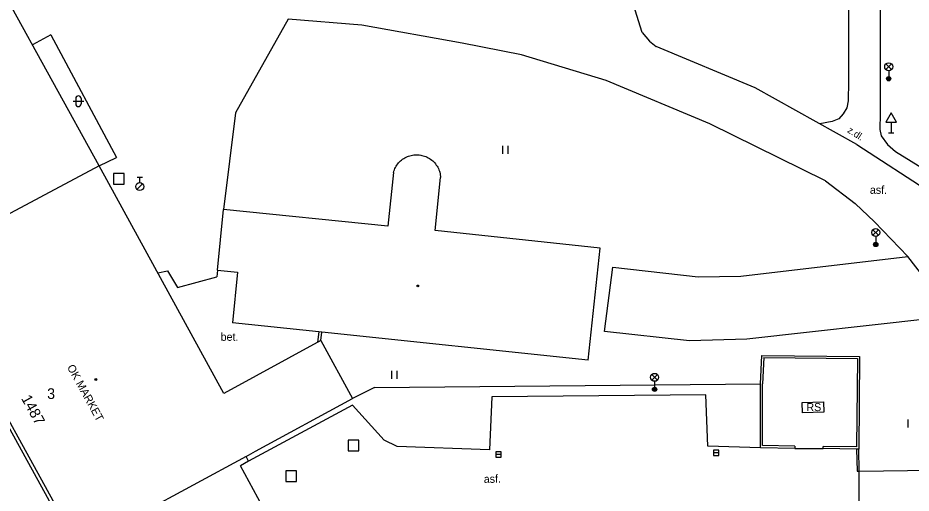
# Model space of a CAD drawing. Extents: x -641829 to -641525, y -1114855 to -1114359.
# Drawn here: x -641715.8 to -641632.1, y -1114774 to -1114729.4 of the extents above; entities that cross this region are included whole.
import ezdxf

# ---------------------------------------------------------------- set-up
doc = ezdxf.new("R2010")
doc.units = 0
for name, color, linetype in [('Vrstva 10', 7, 'Continuous'), ('Vrstva 11', 7, 'Continuous'), ('Vrstva 24', 7, 'Continuous'), ('Vrstva 26', 7, 'Continuous'), ('Vrstva 27', 7, 'Continuous'), ('Vrstva 28', 7, 'Continuous'), ('Vrstva 33', 7, 'Continuous'), ('Vrstva 34', 7, 'Continuous'), ('Vrstva 36', 7, 'Continuous'), ('Vrstva 39', 7, 'Continuous'), ('Vrstva 40', 7, 'Continuous'), ('Vrstva 41', 7, 'Continuous'), ('Vrstva 46', 7, 'Continuous'), ('Vrstva 47', 7, 'Continuous'), ('Vrstva 5', 7, 'Continuous'), ('Vrstva 7', 7, 'Continuous'), ('Vrstva 8', 7, 'Continuous')]:
    doc.layers.add(name, color=color, linetype=linetype)

msp = doc.modelspace()

# ---------------------------------------------------------------- linework, layer by layer
at = {"layer": 'Vrstva 10'}
for p, q in [((-641657.27, -1114730.81), (-641658.08, -1114728.2)), ((-641690.43, -1114729.55), (-641695.37, -1114738.35)), ((-641683.55, -1114730.13), (-641690.43, -1114729.55)), ((-641674.12, -1114731.81), (-641683.55, -1114730.13)), ((-641657.27, -1114730.81), (-641656.57, -1114731.63)), ((-641668.56, -1114732.9), (-641674.12, -1114731.81)), ((-641656.57, -1114731.63), (-641655.95, -1114732.11)), ((-641646.66, -1114736), (-641655.95, -1114732.11)), ((-641660.64, -1114735.29), (-641668.56, -1114732.9)), ((-641650.91, -1114739.36), (-641660.64, -1114735.29)), ((-641637.13, -1114741.3), (-641646.66, -1114736)), ((-641695.37, -1114738.35), (-641696.5, -1114747.41)), ((-641640.08, -1114744.71), (-641650.91, -1114739.36)), ((-641637.13, -1114741.3), (-641629.1, -1114746.53)), ((-641640.08, -1114744.71), (-641637.3, -1114746.85)), ((-641637.3, -1114746.85), (-641635.5, -1114748.55)), ((-641635.5, -1114748.55), (-641632.38, -1114751.79)), ((-641648.02, -1114753.66), (-641632.38, -1114751.79)), ((-641628.04, -1114757.4), (-641632.38, -1114751.79)), ((-641660.78, -1114758.84), (-641660.01, -1114752.82)), ((-641660.01, -1114752.82), (-641652.02, -1114753.72)), ((-641652.02, -1114753.72), (-641648.02, -1114753.66)), ((-641628.04, -1114757.4), (-641647.46, -1114759.57)), ((-641652.83, -1114759.71), (-641660.78, -1114758.84)), ((-641647.46, -1114759.57), (-641652.83, -1114759.71)), ((-641636.92, -1114771.92), (-641627.91, -1114771.8))]:
    msp.add_line(p, q, dxfattribs=at)
at = {"layer": 'Vrstva 11'}
for p, q in [((-641637.93, -1114723.45), (-641637.93, -1114735.4)), ((-641634.96, -1114723.48), (-641634.97, -1114738.41)), ((-641712.69, -1114731.01), (-641714.4, -1114731.95)), ((-641712.69, -1114731.01), (-641706.53, -1114742.53)), ((-641637.93, -1114735.4), (-641637.95, -1114737.21)), ((-641637.95, -1114737.21), (-641638.07, -1114737.88)), ((-641638.41, -1114738.44), (-641638.84, -1114738.89)), ((-641638.07, -1114737.88), (-641638.41, -1114738.44)), ((-641634.97, -1114738.41), (-641634.98, -1114739.91)), ((-641639.46, -1114739.16), (-641640.62, -1114739.36)), ((-641638.84, -1114738.89), (-641639.46, -1114739.16)), ((-641634.98, -1114739.91), (-641634.85, -1114740.5)), ((-641633.52, -1114741.95), (-641630.58, -1114743.77)), ((-641708.16, -1114743.29), (-641706.53, -1114742.53)), ((-641702.66, -1114753.35), (-641701.74, -1114753.15)), ((-641701.74, -1114753.15), (-641700.82, -1114754.71)), ((-641700.82, -1114754.71), (-641697.14, -1114753.72)), ((-641697.07, -1114753.08), (-641697.14, -1114753.72)), ((-641671.34, -1114764.97), (-641671.56, -1114769.92)), ((-641651.3, -1114764.77), (-641671.34, -1114764.97)), ((-641651.12, -1114769.6), (-641651.3, -1114764.77)), ((-641684.41, -1114765.73), (-641694.15, -1114771)), ((-641681.45, -1114769.02), (-641684.41, -1114765.73)), ((-641680.24, -1114769.62), (-641681.45, -1114769.02)), ((-641671.56, -1114769.92), (-641680.24, -1114769.62)), ((-641646.18, -1114769.74), (-641651.12, -1114769.6))]:
    msp.add_line(p, q, dxfattribs=at)
msp.add_lwpolyline([(-641634.85, -1114740.5), (-641634.28, -1114741.31), (-641633.52, -1114741.95)], dxfattribs=at)
at = {"layer": 'Vrstva 24'}
msp.add_lwpolyline([(-641640.27, -1114765.43), (-641640.24, -1114766.41), (-641642.25, -1114766.47), (-641642.27, -1114765.48), (-641640.27, -1114765.43)], dxfattribs=at)
at = {"layer": 'Vrstva 26'}
for points in [[(-641705.8, -1114744.01), (-641706.8, -1114744.01), (-641706.8, -1114745.01), (-641705.8, -1114745.01)], [(-641683.82, -1114769.02), (-641684.82, -1114769.02), (-641684.82, -1114770.02), (-641683.82, -1114770.02)], [(-641689.65, -1114771.89), (-641690.65, -1114771.89), (-641690.65, -1114772.89), (-641689.65, -1114772.89)]]:
    msp.add_lwpolyline(points, close=True, dxfattribs=at)
at = {"layer": 'Vrstva 27'}
for p, q in [((-641670.48, -1114770.38), (-641670.98, -1114770.38)), ((-641650.07, -1114770.21), (-641650.57, -1114770.21))]:
    msp.add_line(p, q, dxfattribs=at)
for points in [[(-641670.48, -1114770.13), (-641670.98, -1114770.13), (-641670.98, -1114770.63), (-641670.48, -1114770.63)], [(-641650.07, -1114769.96), (-641650.57, -1114769.96), (-641650.57, -1114770.46), (-641650.07, -1114770.46)]]:
    msp.add_lwpolyline(points, close=True, dxfattribs=at)
at = {"layer": 'Vrstva 28'}
for p, q in [((-641704.6, -1114744.374), (-641704.1, -1114744.374)), ((-641704.35, -1114744.874), (-641704.35, -1114744.374)), ((-641704.608, -1114745.522), (-641704.078, -1114744.992))]:
    msp.add_line(p, q, dxfattribs=at)
msp.add_circle((-641704.35, -1114745.25), 0.375, dxfattribs=at)
at = {"layer": 'Vrstva 33'}
for p, q in [((-641634.425, -1114734.28), (-641633.895, -1114733.75)), ((-641634.425, -1114733.75), (-641633.895, -1114734.28)), ((-641634.16, -1114734.39), (-641634.16, -1114735.14)), ((-641635.634, -1114749.82), (-641635.106, -1114749.29)), ((-641635.634, -1114749.29), (-641635.106, -1114749.82)), ((-641635.37, -1114749.93), (-641635.37, -1114750.68)), ((-641656.364, -1114763.4), (-641655.836, -1114762.87)), ((-641656.364, -1114762.87), (-641655.836, -1114763.4)), ((-641656.1, -1114763.51), (-641656.1, -1114764.26))]:
    msp.add_line(p, q, dxfattribs=at)
for centre, radius in [((-641634.16, -1114734.015), 0.375), ((-641634.16, -1114735.14), 0.2), ((-641634.16, -1114735.14), 0.145), ((-641634.16, -1114735.14), 0.0876), ((-641635.37, -1114749.555), 0.375), ((-641635.37, -1114750.68), 0.2), ((-641635.37, -1114750.68), 0.145), ((-641635.37, -1114750.68), 0.0876), ((-641656.1, -1114763.135), 0.375), ((-641656.1, -1114764.26), 0.2), ((-641656.1, -1114764.26), 0.145), ((-641656.1, -1114764.26), 0.0876)]:
    msp.add_circle(centre, radius, dxfattribs=at)
at = {"layer": 'Vrstva 34'}
for p, q in [((-641633.92, -1114739.202), (-641633.92, -1114740.22)), ((-641634.17, -1114740.22), (-641633.67, -1114740.22))]:
    msp.add_line(p, q, dxfattribs=at)
msp.add_lwpolyline([(-641634.42, -1114739.202), (-641633.42, -1114739.202), (-641633.92, -1114738.336)], close=True, dxfattribs=at)
at = {"layer": 'Vrstva 36'}
for p, q in [((-641710.596, -1114737.246), (-641709.596, -1114737.246)), ((-641710.346, -1114736.996), (-641710.346, -1114737.496)), ((-641709.846, -1114736.996), (-641709.846, -1114737.496)), ((-641670.314, -1114742.184), (-641670.314, -1114741.432)), ((-641669.814, -1114742.184), (-641669.814, -1114741.432)), ((-641680.714, -1114763.264), (-641680.714, -1114762.512)), ((-641680.214, -1114763.264), (-641680.214, -1114762.512)), ((-641632.344, -1114767.834), (-641632.344, -1114767.082))]:
    msp.add_line(p, q, dxfattribs=at)
for centre, start, end in [((-641710.096, -1114736.996), 0, 180), ((-641710.096, -1114737.496), 180, 0)]:
    msp.add_arc(centre, 0.25, start, end, dxfattribs=at)
at = {"layer": 'Vrstva 39'}
for centre, radius in [((-641678.3, -1114754.57), 0.09), ((-641678.3, -1114754.57), 0.0398), ((-641708.47, -1114763.33), 0.09), ((-641708.47, -1114763.33), 0.0398)]:
    msp.add_circle(centre, radius, dxfattribs=at)
at = {"layer": 'Vrstva 5'}
for p, q in [((-641708.16, -1114743.29), (-641722.9, -1114716.52)), ((-641679.91, -1114742.85), (-641679.81, -1114742.77)), ((-641679.81, -1114742.77), (-641679.71, -1114742.69)), ((-641679.71, -1114742.69), (-641679.61, -1114742.62)), ((-641679.61, -1114742.62), (-641679.5, -1114742.56)), ((-641679.5, -1114742.56), (-641679.39, -1114742.5)), ((-641679.39, -1114742.5), (-641679.27, -1114742.44)), ((-641679.27, -1114742.44), (-641679.15, -1114742.4)), ((-641679.15, -1114742.4), (-641679.03, -1114742.36)), ((-641679.03, -1114742.36), (-641678.91, -1114742.33)), ((-641678.91, -1114742.33), (-641678.78, -1114742.3)), ((-641678.78, -1114742.3), (-641678.66, -1114742.28)), ((-641678.66, -1114742.28), (-641678.53, -1114742.27)), ((-641678.53, -1114742.27), (-641678.4, -1114742.27)), ((-641678.4, -1114742.27), (-641678.28, -1114742.27)), ((-641678.28, -1114742.27), (-641678.15, -1114742.28)), ((-641678.15, -1114742.28), (-641678.02, -1114742.3)), ((-641678.02, -1114742.3), (-641677.9, -1114742.32)), ((-641677.9, -1114742.32), (-641677.78, -1114742.36)), ((-641677.78, -1114742.36), (-641677.65, -1114742.39)), ((-641677.65, -1114742.39), (-641677.54, -1114742.44)), ((-641677.54, -1114742.44), (-641677.42, -1114742.49)), ((-641677.42, -1114742.49), (-641677.31, -1114742.55)), ((-641677.31, -1114742.55), (-641677.2, -1114742.62)), ((-641677.2, -1114742.62), (-641677.09, -1114742.69)), ((-641677.09, -1114742.69), (-641676.99, -1114742.76)), ((-641676.99, -1114742.76), (-641676.89, -1114742.85)), ((-641696.48, -1114764.66), (-641708.16, -1114743.29)), ((-641680.53, -1114743.8), (-641680.49, -1114743.68)), ((-641680.49, -1114743.68), (-641680.44, -1114743.57)), ((-641680.44, -1114743.57), (-641680.38, -1114743.45)), ((-641680.38, -1114743.45), (-641680.31, -1114743.34)), ((-641680.31, -1114743.34), (-641680.25, -1114743.24)), ((-641680.25, -1114743.24), (-641680.17, -1114743.13)), ((-641680.17, -1114743.13), (-641680.09, -1114743.03)), ((-641680.09, -1114743.03), (-641680, -1114742.94)), ((-641680, -1114742.94), (-641679.91, -1114742.85)), ((-641676.89, -1114742.85), (-641676.8, -1114742.93)), ((-641676.8, -1114742.93), (-641676.71, -1114743.02)), ((-641676.71, -1114743.02), (-641676.63, -1114743.12)), ((-641676.63, -1114743.12), (-641676.56, -1114743.23)), ((-641676.56, -1114743.23), (-641676.49, -1114743.33)), ((-641676.49, -1114743.33), (-641676.42, -1114743.44)), ((-641676.42, -1114743.44), (-641676.36, -1114743.56)), ((-641676.36, -1114743.56), (-641676.31, -1114743.67)), ((-641676.31, -1114743.67), (-641676.27, -1114743.79)), ((-641680.57, -1114743.92), (-641681.11, -1114748.96)), ((-641680.57, -1114743.92), (-641680.53, -1114743.8)), ((-641676.66, -1114749.38), (-641676.15, -1114744.4)), ((-641676.27, -1114743.79), (-641676.23, -1114743.91)), ((-641676.23, -1114743.91), (-641676.2, -1114744.04)), ((-641676.2, -1114744.04), (-641676.18, -1114744.16)), ((-641676.18, -1114744.16), (-641676.16, -1114744.29)), ((-641676.16, -1114744.29), (-641676.15, -1114744.4)), ((-641697.07, -1114753.08), (-641696.5, -1114747.41)), ((-641681.11, -1114748.96), (-641696.5, -1114747.41)), ((-641661.21, -1114751.02), (-641676.66, -1114749.38)), ((-641662.32, -1114761.51), (-641661.21, -1114751.02)), ((-641697.07, -1114753.08), (-641695.18, -1114753.27)), ((-641695.18, -1114753.27), (-641695.67, -1114758.01)), ((-641687.58, -1114758.86), (-641695.67, -1114758.01)), ((-641687.29, -1114758.89), (-641687.58, -1114758.86)), ((-641662.32, -1114761.51), (-641687.29, -1114758.89)), ((-641687.37, -1114759.67), (-641696.48, -1114764.66)), ((-641687.37, -1114759.67), (-641684.4, -1114765.11)), ((-641693.49, -1114770.07), (-641684.4, -1114765.11)), ((-641694.39, -1114770.55), (-641693.49, -1114770.07)), ((-641694.39, -1114770.55), (-641707.75, -1114777.77)), ((-641694.15, -1114771), (-641694.91, -1114771.42)), ((-641694.15, -1114771), (-641694.39, -1114770.55)), ((-641692.18, -1114776.44), (-641694.91, -1114771.42))]:
    msp.add_line(p, q, dxfattribs=at)
for points in [[(-641708.16, -1114743.29), (-641724.87, -1114752.22), (-641725.13, -1114752.36)], [(-641710.37, -1114779.19), (-641722.47, -1114757.2), (-641723.61, -1114755.13), (-641725.13, -1114752.36)], [(-641724.87, -1114752.22), (-641723.34, -1114754.99), (-641722.2, -1114757.06), (-641710.1, -1114779.05)]]:
    msp.add_lwpolyline(points, dxfattribs=at)
at = {"layer": 'Vrstva 7'}
for p, q in [((-641687.58, -1114758.86), (-641687.69, -1114759.85)), ((-641687.37, -1114759.67), (-641687.29, -1114758.89)), ((-641646.17, -1114763.73), (-641646.05, -1114761.09)), ((-641646.05, -1114761.09), (-641636.89, -1114761.18)), ((-641636.89, -1114761.18), (-641636.97, -1114769.86)), ((-641645.86, -1114761.29), (-641645.97, -1114763.74)), ((-641645.86, -1114761.29), (-641637.09, -1114761.38)), ((-641637.09, -1114761.38), (-641637.17, -1114769.66)), ((-641682.35, -1114764.1), (-641646.17, -1114763.73)), ((-641646.18, -1114769.74), (-641646.17, -1114763.73)), ((-641645.98, -1114769.54), (-641645.97, -1114763.74)), ((-641682.35, -1114764.1), (-641684.4, -1114765.11)), ((-641642.95, -1114769.6), (-641645.98, -1114769.54)), ((-641642.95, -1114769.6), (-641642.95, -1114769.8)), ((-641640.3, -1114769.81), (-641640.3, -1114769.61)), ((-641637.17, -1114769.66), (-641640.3, -1114769.61)), ((-641642.95, -1114769.8), (-641646.18, -1114769.74)), ((-641637.17, -1114769.86), (-641640.3, -1114769.81)), ((-641636.97, -1114769.86), (-641637.17, -1114769.86)), ((-641637.17, -1114769.86), (-641637.12, -1114771.92)), ((-641636.92, -1114771.92), (-641636.97, -1114769.86)), ((-641637.12, -1114771.92), (-641636.92, -1114771.92))]:
    msp.add_line(p, q, dxfattribs=at)
at = {"layer": 'Vrstva 8'}
for p, q in [((-641642.95, -1114769.8), (-641640.3, -1114769.81)), ((-641636.93, -1114779.85), (-641636.92, -1114771.92))]:
    msp.add_line(p, q, dxfattribs=at)

# ---------------------------------------------------------------- texts
at = {"layer": 'Vrstva 40'}
msp.add_text('z.dl.', height=0.65, rotation=327.26747, dxfattribs=at).set_placement((-641638.09, -1114740.12))
at = {"layer": 'Vrstva 41'}
for s, p in [('asf.', (-641635.92, -1114745.93)), ('bet.', (-641696.77, -1114759.71)), ('RS', (-641641.87, -1114766.3))]:
    msp.add_text(s, height=0.75, dxfattribs=at).set_placement(p)
for s, height, rotation, p in [('OK MARKET', 0.75, 298.82145, (-641711.19, -1114762.18)), ('asf.', 0.7499, 1.75663, (-641672.1, -1114773.05))]:
    msp.add_text(s, height=height, rotation=rotation, dxfattribs=at).set_placement(p)
at = {"layer": 'Vrstva 46'}
msp.add_text('3', height=1, dxfattribs=at).set_placement((-641713.03, -1114765.16))
at = {"layer": 'Vrstva 47'}
msp.add_text('1487', height=1, rotation=298.81981, dxfattribs=at).set_placement((-641715.49, -1114765.11))

doc.saveas('drawing.dxf')
